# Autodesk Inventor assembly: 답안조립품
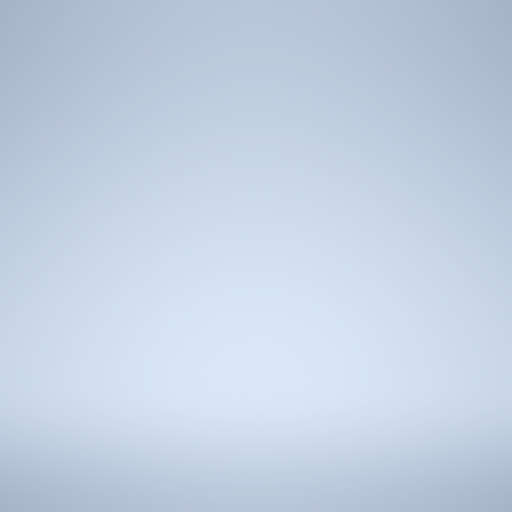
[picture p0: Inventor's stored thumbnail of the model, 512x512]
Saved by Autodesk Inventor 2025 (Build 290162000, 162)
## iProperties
Created: 2026-01
Part Number: 답안조립품
Document SubType Name: Assembly
Designer: KDI
Author: KDI
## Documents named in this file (1)
- C:\Users\KDI\Desktop\760103V1017\답안조립품.iam
